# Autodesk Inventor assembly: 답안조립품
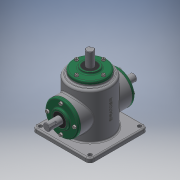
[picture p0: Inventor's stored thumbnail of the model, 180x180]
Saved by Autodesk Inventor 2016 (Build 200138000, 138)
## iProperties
Created: 2019-08
Part Number: 답안조립품
Material: 일반
Document SubType Name: Assembly
Designer: user
Author: user
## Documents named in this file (16)
- D:\490823V1006\답안조립품.iam
- D:\490823V1006\메인 베벨기어.ipt
- D:\490823V1006\메인 축.ipt
- 메인 축.ipt
- D:\490823V1006\베어링 6203.ipt
- D:\490823V1006\본체.ipt
- D:\490823V1006\볼트 M4.ipt
- 볼트 M4.ipt
- D:\490823V1006\서브 베벨기어.ipt
- D:\490823V1006\서브 축.ipt
- 서브 축.ipt
- D:\490823V1006\오일 실.ipt
- 오일 실.ipt
- D:\490823V1006\커버.ipt
- D:\490823V1006\키 5x5.ipt
- D:\490823V1006\키 4x4.ipt
